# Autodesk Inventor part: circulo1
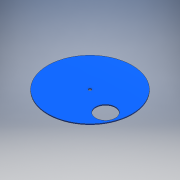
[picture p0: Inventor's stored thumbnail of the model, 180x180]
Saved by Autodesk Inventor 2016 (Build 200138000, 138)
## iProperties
Created: 2016-06
Part Number: circulo1
Material: Genérico
Document SubType Name: Modeling
Designer: adm
Density: 1 g/cm^3
Appearance: Valor por defecto
Author: adm
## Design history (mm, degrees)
sketch "Boceto1"
  geometry: C1 r 150 at (0, 0); C2 r 35 at (98.496, -43.002); C3 r 5 at (0, 0); 1 further point
  constraints: 3 centre point, 2 coincident
  dimensions: "d0" = 300 diameter of C1; "d2" = 10 diameter of C3
extrude "Extrusión1" new body sketch "Boceto1" distance "d3" = 3; taper "d4" = 0 deg
node "Sólido1"
